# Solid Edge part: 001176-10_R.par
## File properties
Last saved by: morva
Revision: 82
Accuracy: 0.990
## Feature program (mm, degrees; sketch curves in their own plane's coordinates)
body "unnamed Body 1"
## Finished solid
Body 1: solid body, 32 faces, 67 edges, 38 vertices.
  Faces by surface: cone 11, torus 10, plane 9, cylinder 2
  Edges by curve: circle 37, line 19, curve on surface 7, spline 4
Bounding box of the edges (mm; curved faces can reach further): 12.111 x 22.090 x 14.346, from (390.8082, 375.5926, 167.1421) to (402.9189, 397.6821, 181.488).
Cylindrical faces by radius (mm): R2.5 x2
Conical faces (half-angle, radius in mm at the cone's reference point): 45 deg R2.3094 x7, 45 deg R2.5 x2, 45 deg R4.4561 x2
Toroidal faces (ring radius, tube radius in mm): R0.6241 r3.9478 x2, R2.7 r0.2 x2, R3.5613 r1 x4, R4.3147 r0.2 x2
Planar faces by outward normal: oblique 9
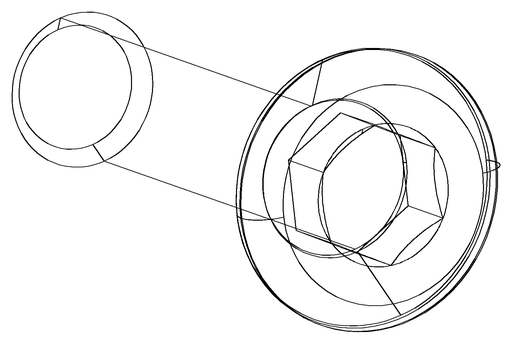
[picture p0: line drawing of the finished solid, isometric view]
